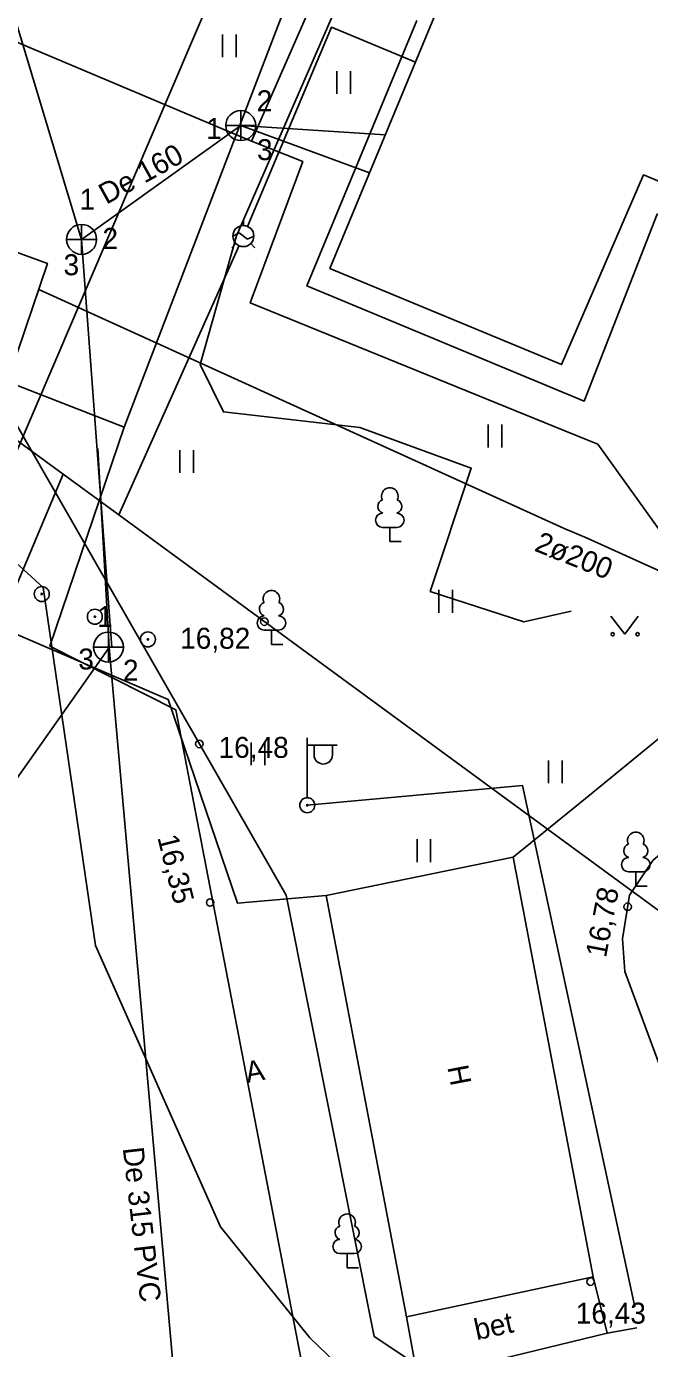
# Model space of a CAD drawing. Extents: x 713540 to 713867, y 6589774 to 6590061.
# Drawn here: x 713630.69 to 713651.49, y 6589871.64 to 6589915.75 of the extents above; entities that cross this region are included whole.
import ezdxf

# ---------------------------------------------------------------- set-up
doc = ezdxf.new("R2010")
doc.units = 0
for name, color, linetype in [('HALJASTUS', 7, 'Continuous'), ('HOONE', 7, 'Continuous'), ('HOONEDET', 7, 'Continuous'), ('KKAEV', 7, 'Continuous'), ('KORGUS', 7, 'Continuous'), ('KTRASS', 7, 'Continuous'), ('MPKAABEL', 7, 'Continuous'), ('POST', 7, 'Continuous'), ('PUU', 7, 'Continuous'), ('SITRASS', 7, 'Continuous'), ('TEE', 7, 'Continuous'), ('TORU NR', 7, 'Continuous'), ('TTRASS', 7, 'Continuous'), ('Слой 1', 7, 'Continuous')]:
    doc.layers.add(name, color=color, linetype=linetype)

msp = doc.modelspace()

# ---------------------------------------------------------------- linework, layer by layer
at = {"layer": 'HALJASTUS'}
for p, q in [((713637.234, 6589915.479), (713637.234, 6589914.718)), ((713637.689, 6589915.479), (713637.689, 6589914.718)), ((713641.054, 6589914.259), (713641.054, 6589913.498)), ((713641.509, 6589914.259), (713641.509, 6589913.498)), ((713646.101, 6589902.464), (713646.101, 6589901.703)), ((713646.556, 6589902.464), (713646.556, 6589901.703)), ((713635.808, 6589901.616), (713635.808, 6589900.855)), ((713636.263, 6589901.616), (713636.263, 6589900.855)), ((713644.456, 6589896.949), (713644.456, 6589896.188)), ((713644.911, 6589896.949), (713644.911, 6589896.188)), ((713650.197, 6589896.077), (713650.66, 6589895.47)), ((713650.66, 6589895.47), (713651.106, 6589896.077)), ((713638.187, 6589891.858), (713638.187, 6589891.097)), ((713638.642, 6589891.858), (713638.642, 6589891.097)), ((713648.114, 6589891.259), (713648.114, 6589890.497)), ((713648.569, 6589891.259), (713648.569, 6589890.497)), ((713643.727, 6589888.628), (713643.727, 6589887.867)), ((713644.182, 6589888.628), (713644.182, 6589887.867))]:
    msp.add_line(p, q, dxfattribs=at)
for centre in [(713650.259, 6589895.47), (713651.088, 6589895.47)]:
    msp.add_circle(centre, 0.055, dxfattribs=at)
at = {"layer": 'HOONE'}
for p, q in [((713637.929, 6589909.103), (713637.929, 6589909.301)), ((713637.579, 6589908.751), (713637.791, 6589908.857)), ((713637.791, 6589908.857), (713638.068, 6589908.649)), ((713638.068, 6589908.649), (713638.279, 6589908.755)), ((713637.682, 6589908.506), (713637.542, 6589908.366)), ((713638.177, 6589908.506), (713638.317, 6589908.366))]:
    msp.add_line(p, q, dxfattribs=at)
for points in [[(713621.704, 6589881.367), (713643.483, 6589932.26)], [(713649.497, 6589928.594), (713640.819, 6589907.673), (713648.554, 6589904.463), (713651.284, 6589910.794), (713661.288, 6589906.631), (713663.51, 6589903.92), (713662.91, 6589903.51), (713666.09, 6589899.51), (713666.61, 6589899.89), (713668.88, 6589896.79), (713670.52, 6589886.24), (713663.68, 6589884.95)], [(713609.43, 6589917.22), (713616.586, 6589911.996), (713631.91, 6589900.81), (713633.77, 6589899.45), (713649.493, 6589887.937), (713658.68, 6589881.21), (713662.78, 6589860.48)], [(713638.066, 6589909.076), (713640.87, 6589915.72), (713643.674, 6589914.557)], [(713633.77, 6589899.45), (713637.787, 6589908.434)], [(713630.171, 6589896.651), (713631.91, 6589900.81)], [(713649.603, 6589874.03), (713643.373, 6589872.699), (713640.697, 6589886.755), (713646.94, 6589888.03), (713649.603, 6589874.03)]]:
    msp.add_lwpolyline(points, dxfattribs=at)
msp.add_circle((713637.929, 6589908.753), 0.35, dxfattribs=at)
at = {"layer": 'HOONEDET'}
msp.add_lwpolyline([(713643.718, 6589915.944), (713640.045, 6589907.089), (713649.308, 6589903.247), (713651.748, 6589909.484), (713660.49, 6589905.59), (713662.88, 6589902.4)], dxfattribs=at)
at = {"layer": 'KKAEV'}
for p, q in [((713637.841, 6589911.937), (713637.841, 6589912.937)), ((713637.341, 6589912.437), (713638.341, 6589912.437)), ((713632.529, 6589908.142), (713632.529, 6589909.142)), ((713632.029, 6589908.642), (713633.029, 6589908.642)), ((713633.426, 6589894.542), (713633.426, 6589895.542)), ((713632.926, 6589895.042), (713633.926, 6589895.042))]:
    msp.add_line(p, q, dxfattribs=at)
for centre in [(713637.841, 6589912.437), (713632.529, 6589908.642), (713633.426, 6589895.042)]:
    msp.add_circle(centre, 0.5, dxfattribs=at)
at = {"layer": 'KORGUS'}
for centre in [(713638.63, 6589895.89), (713636.46, 6589891.81), (713636.82, 6589886.52), (713650.76, 6589886.38), (713649.52, 6589873.87)]:
    msp.add_circle(centre, 0.125, dxfattribs=at)
at = {"layer": 'KTRASS'}
for p, q in [((713618.35, 6589955.601), (713632.529, 6589908.642)), ((713632.529, 6589908.642), (713637.841, 6589912.437)), ((713637.841, 6589912.437), (713642.665, 6589912.125)), ((713637.841, 6589912.437), (713642.142, 6589910.864)), ((713632.529, 6589908.642), (713633.533, 6589895.029))]:
    msp.add_line(p, q, dxfattribs=at)
for points in [[(713633.067, 6589901.664), (713633.446, 6589895.028)], [(713627.826, 6589887.076), (713633.446, 6589895.028)], [(713633.446, 6589895.028), (713635.943, 6589867.043)]]:
    msp.add_lwpolyline(points, dxfattribs=at)
at = {"layer": 'MPKAABEL'}
for points in [[(713539.965, 6589974.853), (713543.131, 6589973.53), (713546.108, 6589972.287), (713566.322, 6589963.707), (713573.773, 6589960.702), (713592.786, 6589952.579), (713613.42, 6589943.422), (713617.199, 6589942.481), (713626.863, 6589938.886), (713639.576, 6589933.635), (713646.471, 6589931.372), (713643, 6589921.63), (713641.284, 6589916.978), (713637.701, 6589908.759), (713636.487, 6589904.472), (713637.263, 6589902.886), (713641.82, 6589902.37), (713645.539, 6589901.01), (713644.167, 6589896.896), (713647.29, 6589895.882), (713648.871, 6589896.241)], [(713621.405, 6589921.156), (713617.009, 6589909.766), (713616.379, 6589906.228), (713617.893, 6589905.104), (713618.264, 6589904.829), (713628.654, 6589899.391), (713631.248, 6589897.024), (713632.991, 6589885.086), (713637.163, 6589875.703), (713640.145, 6589871.993), (713646.211, 6589866.173), (713649.924, 6589862.847), (713657.342, 6589851.294), (713662.171, 6589845.836), (713664.179, 6589844.049)], [(713640.063, 6589889.766), (713647.25, 6589890.42), (713651.004, 6589873.029)], [(713650.078, 6589872.152), (713651.068, 6589872.335)]]:
    msp.add_lwpolyline(points, dxfattribs=at)
at = {"layer": 'POST'}
for p, q in [((713640.063, 6589890.016), (713640.063, 6589892.016)), ((713640.063, 6589891.766), (713641.063, 6589891.766)), ((713640.29, 6589891.445), (713640.29, 6589891.766)), ((713640.903, 6589891.445), (713640.903, 6589891.766))]:
    msp.add_line(p, q, dxfattribs=at)
for centre, radius in [((713631.2, 6589896.811), 0.25), ((713631.2, 6589896.811), 0.0234), ((713632.971, 6589896.054), 0.25), ((713632.971, 6589896.054), 0.0234), ((713634.742, 6589895.298), 0.25), ((713634.742, 6589895.298), 0.0234), ((713640.063, 6589889.766), 0.25), ((713640.063, 6589889.766), 0.0234)]:
    msp.add_circle(centre, radius, dxfattribs=at)
msp.add_arc((713640.596, 6589891.445), 0.306, 180, 0, dxfattribs=at)
at = {"layer": 'PUU'}
for p, q in [((713643.058, 6589899.035), (713642.578, 6589899.035)), ((713642.818, 6589898.56), (713642.818, 6589899.035)), ((713643.198, 6589898.56), (713642.818, 6589898.56)), ((713639.106, 6589895.607), (713638.626, 6589895.607)), ((713638.866, 6589895.132), (713638.866, 6589895.607)), ((713639.246, 6589895.132), (713638.866, 6589895.132)), ((713651.27, 6589887.545), (713650.79, 6589887.545)), ((713651.03, 6589887.07), (713651.03, 6589887.545)), ((713651.41, 6589887.07), (713651.03, 6589887.07)), ((713641.632, 6589874.806), (713641.152, 6589874.806)), ((713641.392, 6589874.331), (713641.392, 6589874.806)), ((713641.772, 6589874.331), (713641.392, 6589874.331))]:
    msp.add_line(p, q, dxfattribs=at)
for centre, radius, start, end in [((713642.818, 6589900.08), 0.277, 332.5799, 207.4201), ((713642.648, 6589899.733), 0.233, 109.0217, 253.1415), ((713642.988, 6589899.733), 0.233, 286.8508, 70.9859), ((713642.58, 6589899.272), 0.238, 90.0016, 269.3953), ((713643.055, 6589899.272), 0.238, 270.6047, 89.9984), ((713638.866, 6589896.652), 0.277, 332.5799, 207.4201), ((713638.696, 6589896.304), 0.233, 109.0217, 253.1415), ((713639.037, 6589896.304), 0.233, 286.8508, 70.9859), ((713638.629, 6589895.844), 0.238, 90.0016, 269.3953), ((713639.104, 6589895.844), 0.238, 270.6047, 89.9984), ((713651.03, 6589888.59), 0.277, 332.5799, 207.4201), ((713650.86, 6589888.243), 0.233, 109.0217, 253.1415), ((713651.2, 6589888.243), 0.233, 286.8508, 70.9859), ((713650.793, 6589887.782), 0.238, 90.0016, 269.3953), ((713651.267, 6589887.782), 0.238, 270.6047, 89.9984), ((713641.392, 6589875.851), 0.277, 332.5799, 207.4201), ((713641.222, 6589875.504), 0.233, 109.0217, 253.1415), ((713641.562, 6589875.504), 0.233, 286.8508, 70.9859), ((713641.155, 6589875.044), 0.238, 90.0016, 269.3953), ((713641.63, 6589875.044), 0.238, 270.6047, 89.9984)]:
    msp.add_arc(centre, radius, start, end, dxfattribs=at)
at = {"layer": 'SITRASS'}
for points in [[(713680.76, 6589850.01), (713672.23, 6589848.51), (713669.283, 6589865.987), (713667.62, 6589875.84), (713665.21, 6589875.309), (713665.174, 6589875.301), (713663.67, 6589874.97), (713661.62, 6589885.51), (713653.61, 6589896.45), (713649.76, 6589901.81), (713649.429, 6589901.945), (713648.305, 6589902.402), (713638.16, 6589906.53), (713639.91, 6589911.24), (713638.2, 6589911.92), (713614.722, 6589921.827), (713596.94, 6589929.45), (713589.631, 6589932.637), (713589.097, 6589932.87), (713558.329, 6589946.285), (713549.9, 6589949.96), (713539.965, 6589954.262)], [(713622.526, 6589942.802), (713625.02, 6589914.21), (713630.01, 6589903.07), (713639.36, 6589886.76), (713642.3, 6589872.04), (713652.19, 6589865.47), (713653.052, 6589864.917), (713657.52, 6589862.05), (713661.076, 6589847.8), (713664.28, 6589834.96), (713666.33, 6589831.93), (713670.966, 6589832.394), (713671.39, 6589832.436), (713687.742, 6589834.073), (713694.81, 6589834.78), (713711.155, 6589837.134), (713711.376, 6589837.166), (713715.85, 6589837.81)], [(713638.2, 6589911.92), (713646.56, 6589930.97), (713672.28, 6589920.04), (713673.742, 6589918.058), (713674.353, 6589917.232), (713684.25, 6589903.82), (713685.11, 6589899.99), (713694.473, 6589901.366), (713697.757, 6589901.848), (713704.78, 6589902.88), (713705.47, 6589904.42), (713707.4, 6589905.83), (713709.059, 6589905.94)]]:
    msp.add_lwpolyline(points, dxfattribs=at)
at = {"layer": 'TEE'}
for points in [[(713646.94, 6589888.03), (713649.348, 6589889.993), (713658.16, 6589897.2), (713662.62, 6589901.32)], [(713664.5, 6589899), (713660.15, 6589895.36), (713655.26, 6589891.1), (713651.6, 6589887.92), (713650.82, 6589886.76), (713650.59, 6589885.31), (713650.67, 6589884.22), (713653.36, 6589876.96), (713654.18, 6589875.76), (713655.15, 6589874.57), (713656.86, 6589873.47), (713658.69, 6589872.98), (713659.62, 6589872.91), (713665.5, 6589874.051), (713674.688, 6589875.556), (713675.117, 6589876.72)], [(713640.697, 6589886.755), (713637.729, 6589886.497), (713635.42, 6589893.287), (713627.642, 6589896.627)], [(713643.373, 6589872.699), (713643.752, 6589870.615), (713650.078, 6589872.152), (713649.603, 6589874.03)]]:
    msp.add_lwpolyline(points, dxfattribs=at)
at = {"layer": 'TTRASS'}
for points in [[(713628.85, 6589905.4), (713629.96, 6589908.36), (713631.39, 6589907.84), (713630.39, 6589904.88), (713628.85, 6589905.4)], [(713631.1, 6589906.97), (713648.617, 6589899.011), (713649.407, 6589898.677), (713660.15, 6589893.81)]]:
    msp.add_lwpolyline(points, dxfattribs=at)
at = {"layer": 'Слой 1'}
for points in [[(713682.51, 6589917.77), (713690.33, 6589877.18), (713657.78, 6589870.72), (713657.67, 6589868.71), (713640.88, 6589865.96), (713635.67, 6589892.95), (713631.47, 6589895.07), (713633.95, 6589902.38), (713645.78, 6589933.24)], [(713577.92, 6589843.53), (713607.67, 6589912.62), (713633.95, 6589902.38), (713631.47, 6589895.07), (713635.67, 6589892.95), (713640.88, 6589865.96), (713628.08, 6589863.38), (713615.46, 6589827.79)]]:
    msp.add_lwpolyline(points, close=True, dxfattribs=at)

# ---------------------------------------------------------------- texts
at = {"layer": 'HOONE'}
msp.add_text('H', height=0.7, rotation=280.7707, dxfattribs=at).set_placement((713644.737, 6589881.028))
at = {"layer": 'HOONEDET'}
msp.add_text('bet', height=0.7, rotation=12.1873, dxfattribs=at).set_placement((713645.719, 6589871.915))
at = {"layer": 'KORGUS'}
for s, p in [('16,82', (713635.818, 6589894.985)), ('16,48', (713637.101, 6589891.345)), ('16,43', (713649.026, 6589872.47))]:
    msp.add_text(s, height=0.7, dxfattribs=at).set_placement(p)
for s, rotation, p in [('16,35', 284.0474, (713635.055, 6589888.693)), ('16,78', 79.3396, (713650.035, 6589884.654))]:
    msp.add_text(s, height=0.7, rotation=rotation, dxfattribs=at).set_placement(p)
at = {"layer": 'KTRASS'}
for s, rotation, p in [('De 160 ', 28.9677, (713633.352, 6589909.793)), ('De 315 PVC ', 276.5366, (713633.901, 6589878.325))]:
    msp.add_text(s, height=0.7, rotation=rotation, dxfattribs=at).set_placement(p)
at = {"layer": 'TEE'}
msp.add_text('A', height=0.7, rotation=10.613, dxfattribs=at).set_placement((713638.064, 6589880.5))
at = {"layer": 'TORU NR'}
for s, p in [('2', (713638.373, 6589912.917)), ('1', (713636.689, 6589911.994)), ('3', (713638.384, 6589911.286)), ('1', (713632.462, 6589909.634)), ('2', (713633.224, 6589908.325)), ('3', (713631.926, 6589907.446)), ('1', (713633.052, 6589895.709)), ('3', (713632.419, 6589894.293)), ('2', (713633.91, 6589893.918))]:
    msp.add_text(s, height=0.7, dxfattribs=at).set_placement(p)
msp.add_text('2ø200', height=0.7, rotation=338.2729, dxfattribs=at).set_placement((713647.612, 6589898.264))

doc.saveas('drawing.dxf')
